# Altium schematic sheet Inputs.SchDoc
size A4
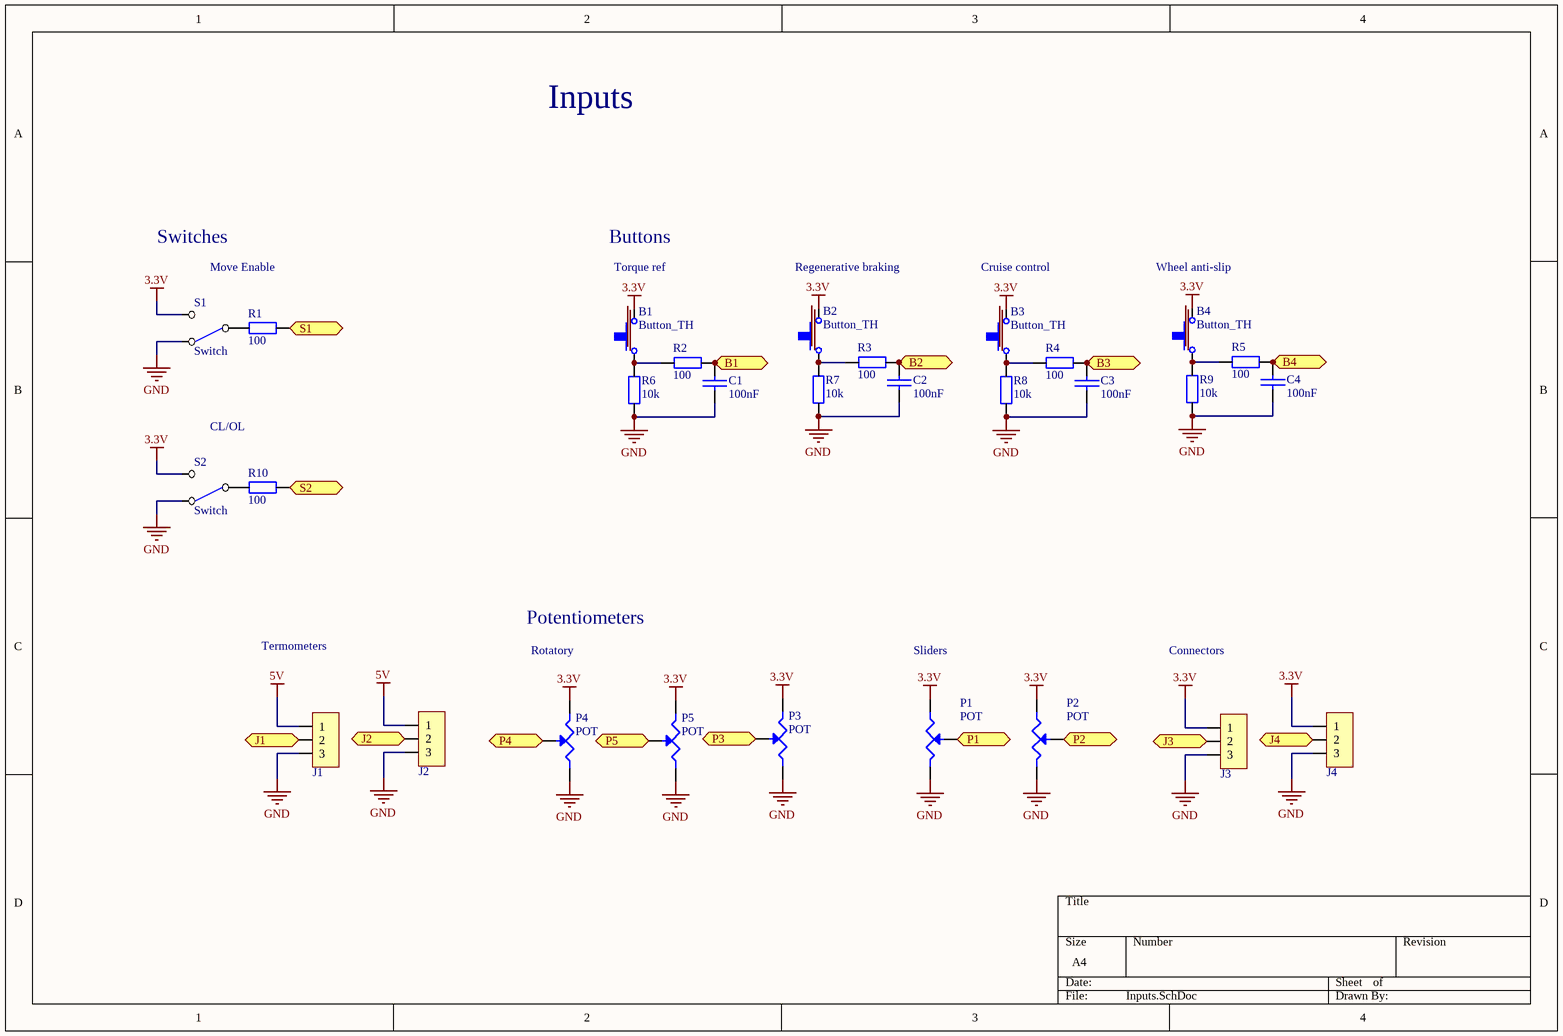
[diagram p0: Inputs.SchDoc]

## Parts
B1  Button_TH  [ButtonTH]
B2  Button_TH  [ButtonTH]
B3  Button_TH  [ButtonTH]
B4  Button_TH  [ButtonTH]
C1  100nF  [1206]
C2  100nF  [1206]
C3  100nF  [1206]
C4  100nF  [1206]
J1  Cleva 2 vias  [Con3_KK_256]  (value not drawn)
J2  Cleva 2 vias  [Con3_KK_256]  (value not drawn)
J3  Cleva 2 vias  [Con3_KK_256]  (value not drawn)
J4  Cleva 2 vias  [Con3_KK_256]  (value not drawn)
P1  POT  [SliderPot_PTA6044]
P2  POT  [SliderPot_PTA6044]
P3  POT  [POT_RK11K1140A3L]
P4  POT  [POT_RK11K1140A3L]
P5  POT  [POT_RK11K1140A3L]
R1  100  [1206]
R2  100  [1206]
R3  100  [1206]
R4  100  [1206]
R5  100  [1206]
R6  10k  [1206]
R7  10k  [1206]
R8  10k  [1206]
R9  10k  [1206]
R10  100  [1206]
S1  Switch  [SwitchTH_2Pos]
S2  Switch  [SwitchTH_2Pos]

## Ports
B1, B2, B3, B4, J1, J2, J3, J4, P1, P2, P3, P4, P5, S1, S2

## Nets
3.3V: B1.0 B2.0 B3.0 B4.0 J3.1 J4.1 P1.1 P2.1 P3.3 P4.3 P5.3 S1.2(ON2) S2.2(ON2)
5V: J1.1 J2.1
GND: C1.2 C2.2 C3.2 C4.2 J1.3 J2.3 J3.3 J4.3 P1.3 P2.3 P3.1 P4.1 P5.1 R6.2 R7.2 R8.2 R9.2 S1.0(ON1) S2.0(ON1)
B1: C1.1 R2.1 ; port B1
B2: C2.1 R3.1 ; port B2
B3: C3.1 R4.1 ; port B3
B4: C4.1 R5.1 ; port B4
J1: J1.2 ; port J1
J2: J2.2 ; port J2
J3: J3.2 ; port J3
J4: J4.2 ; port J4
P1: P1.2 ; port P1
P2: P2.2 ; port P2
P3: P3.2 ; port P3
P4: P4.2 ; port P4
P5: P5.2 ; port P5
S1: R1.2 ; port S1
S2: R10.2 ; port S2
NetB1_1: B1.1 R2.2 R6.1
NetB2_1: B2.1 R3.2 R7.1
NetB3_1: B3.1 R4.2 R8.1
NetB4_1: B4.1 R5.2 R9.1
NetR1_1: R1.1 S1.1(COMMON)
NetR10_1: R10.1 S2.1(COMMON)

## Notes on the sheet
- Inputs
- Switches
- Buttons
- Move Enable
- (near B1) Torque ref
- (near B2) Regenerative braking
- (near B3) Cruise control
- (near B4) Wheel anti-slip
- CL/OL
- Termometers
- Potentiometers
- Rotatory
- (near P1) Sliders
- Connectors

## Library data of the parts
C1-C4 = Condensador
J1-J4 = Con_3
P1-P5 = POT: POTENCIOMETRO
R1-R10 = Resistencia: Potencia: 1/4W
